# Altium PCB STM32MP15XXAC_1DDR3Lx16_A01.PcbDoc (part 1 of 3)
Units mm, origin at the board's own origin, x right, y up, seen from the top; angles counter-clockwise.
Board outline 89 x 120 mm, 4 copper layers (Top Layer, Signal Layer 1, Signal Layer 2, Bottom Layer), stack 1.571 mm thick; 133 components, 92 nets, 915 pads, 400 vias.
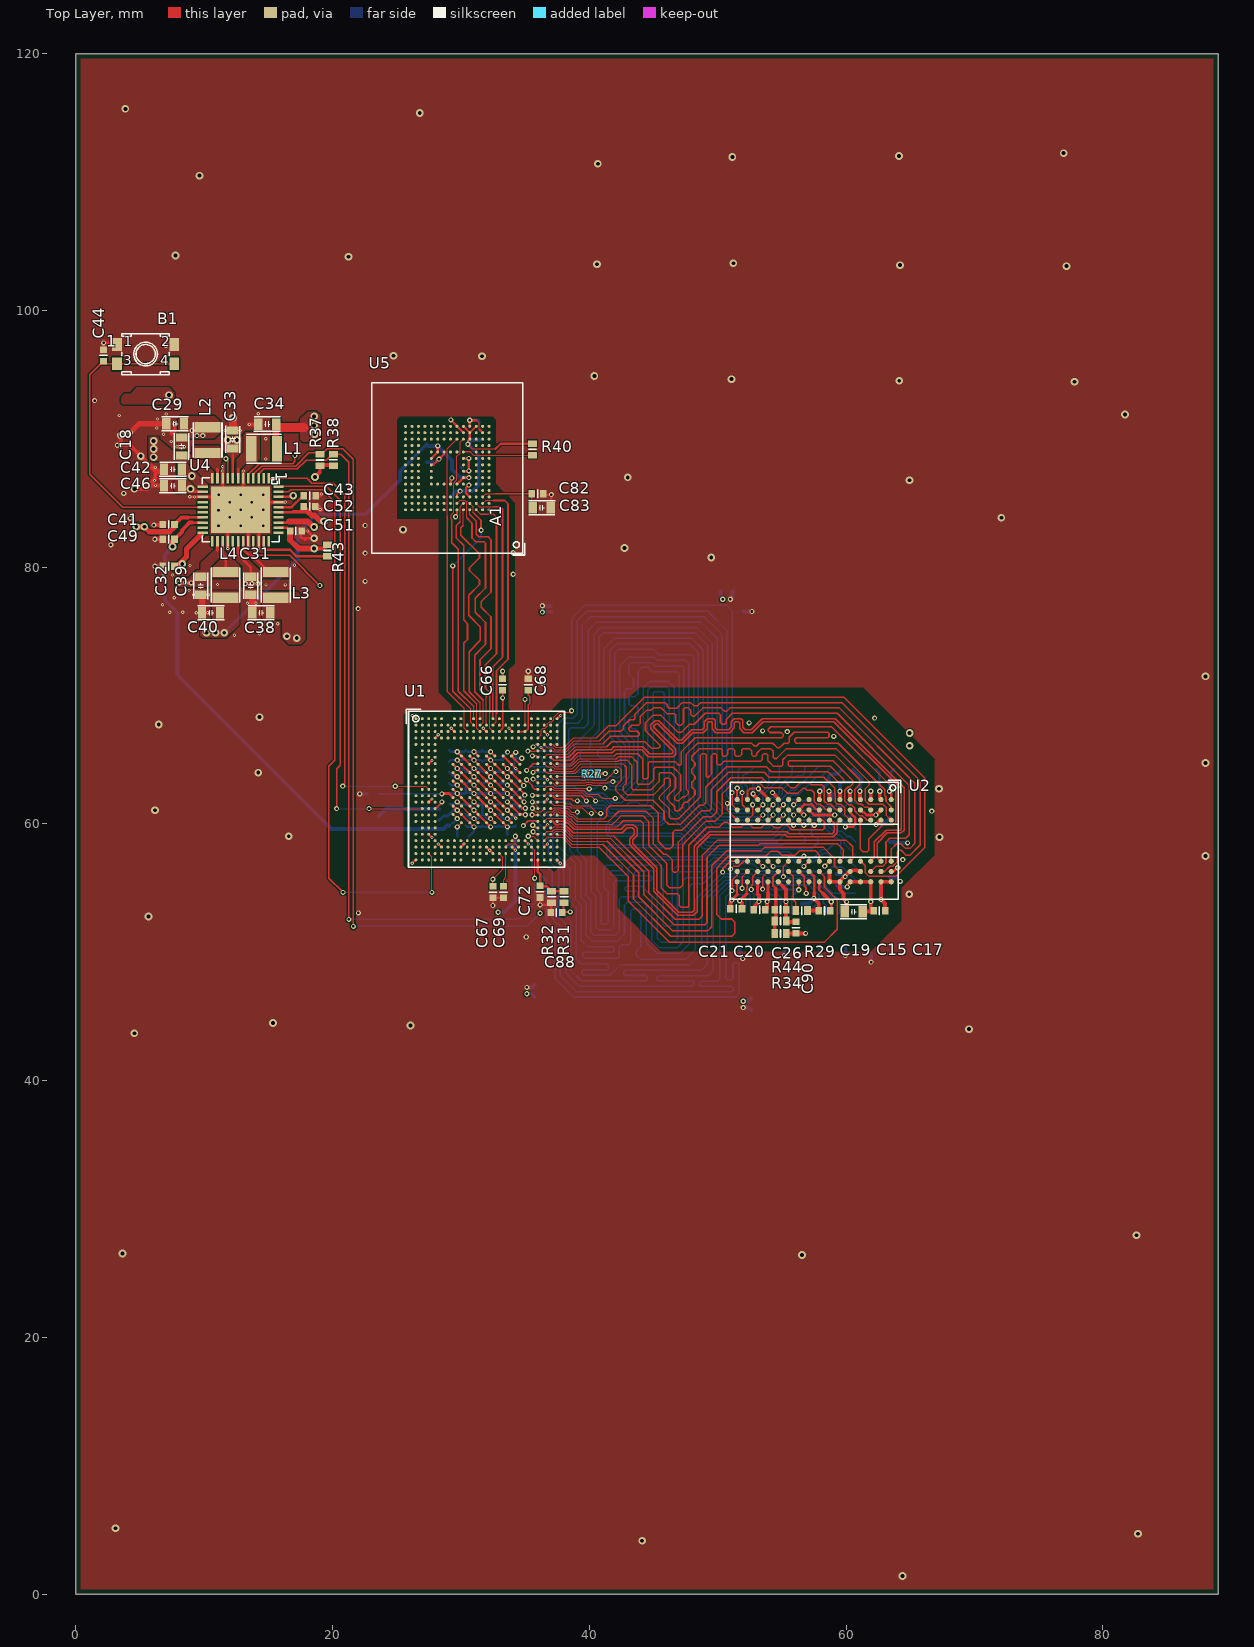
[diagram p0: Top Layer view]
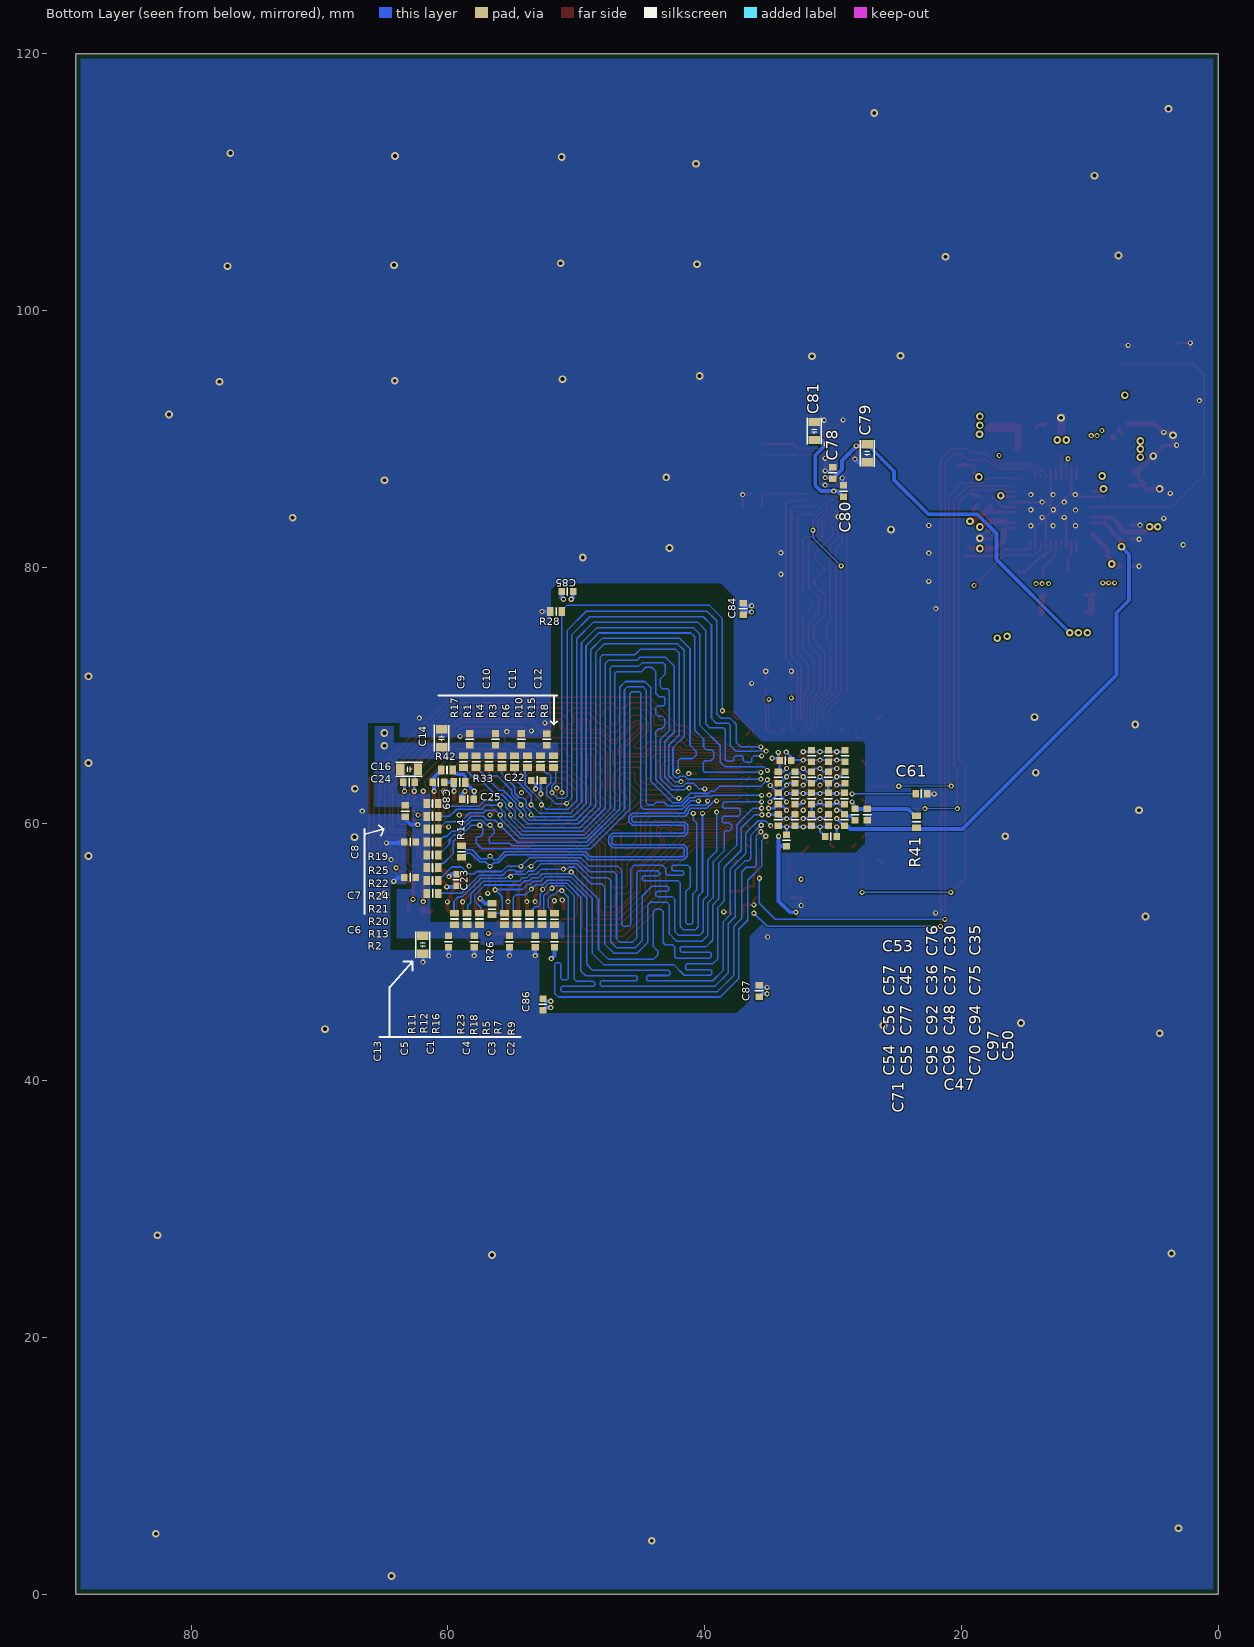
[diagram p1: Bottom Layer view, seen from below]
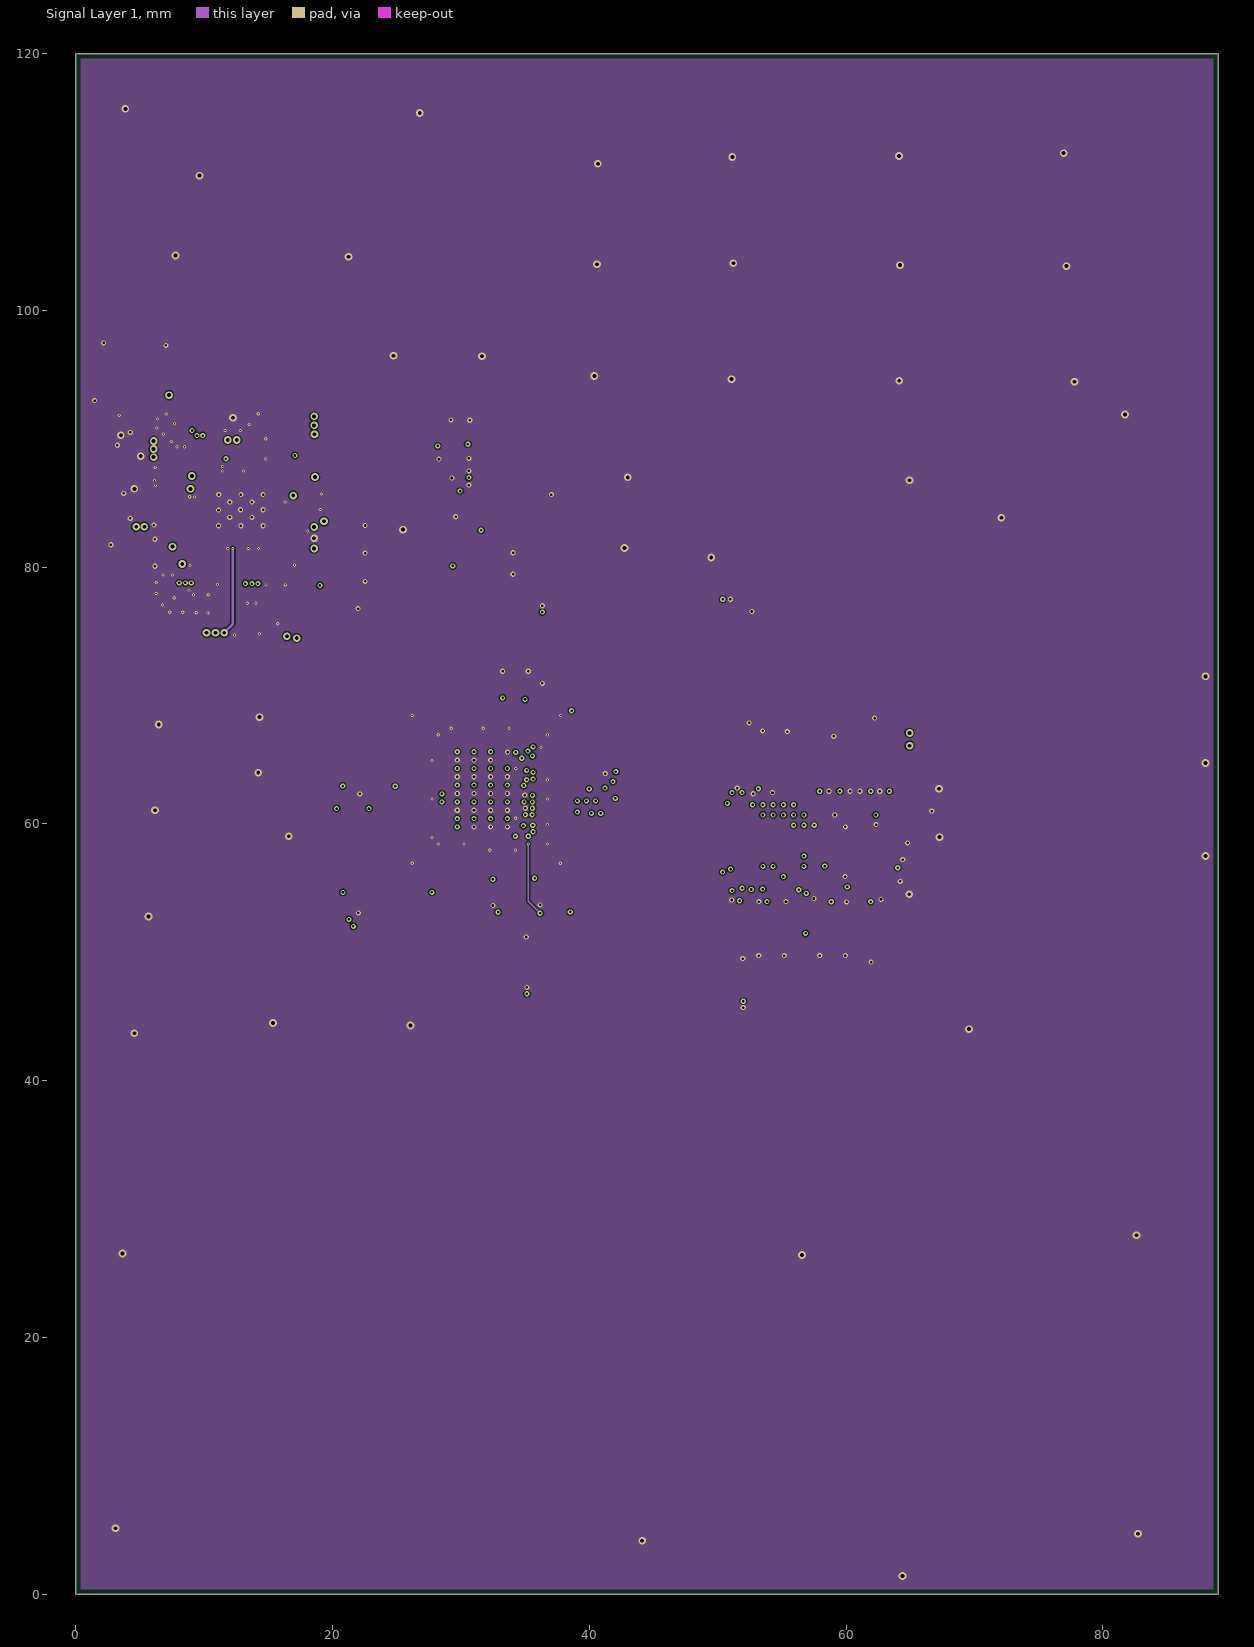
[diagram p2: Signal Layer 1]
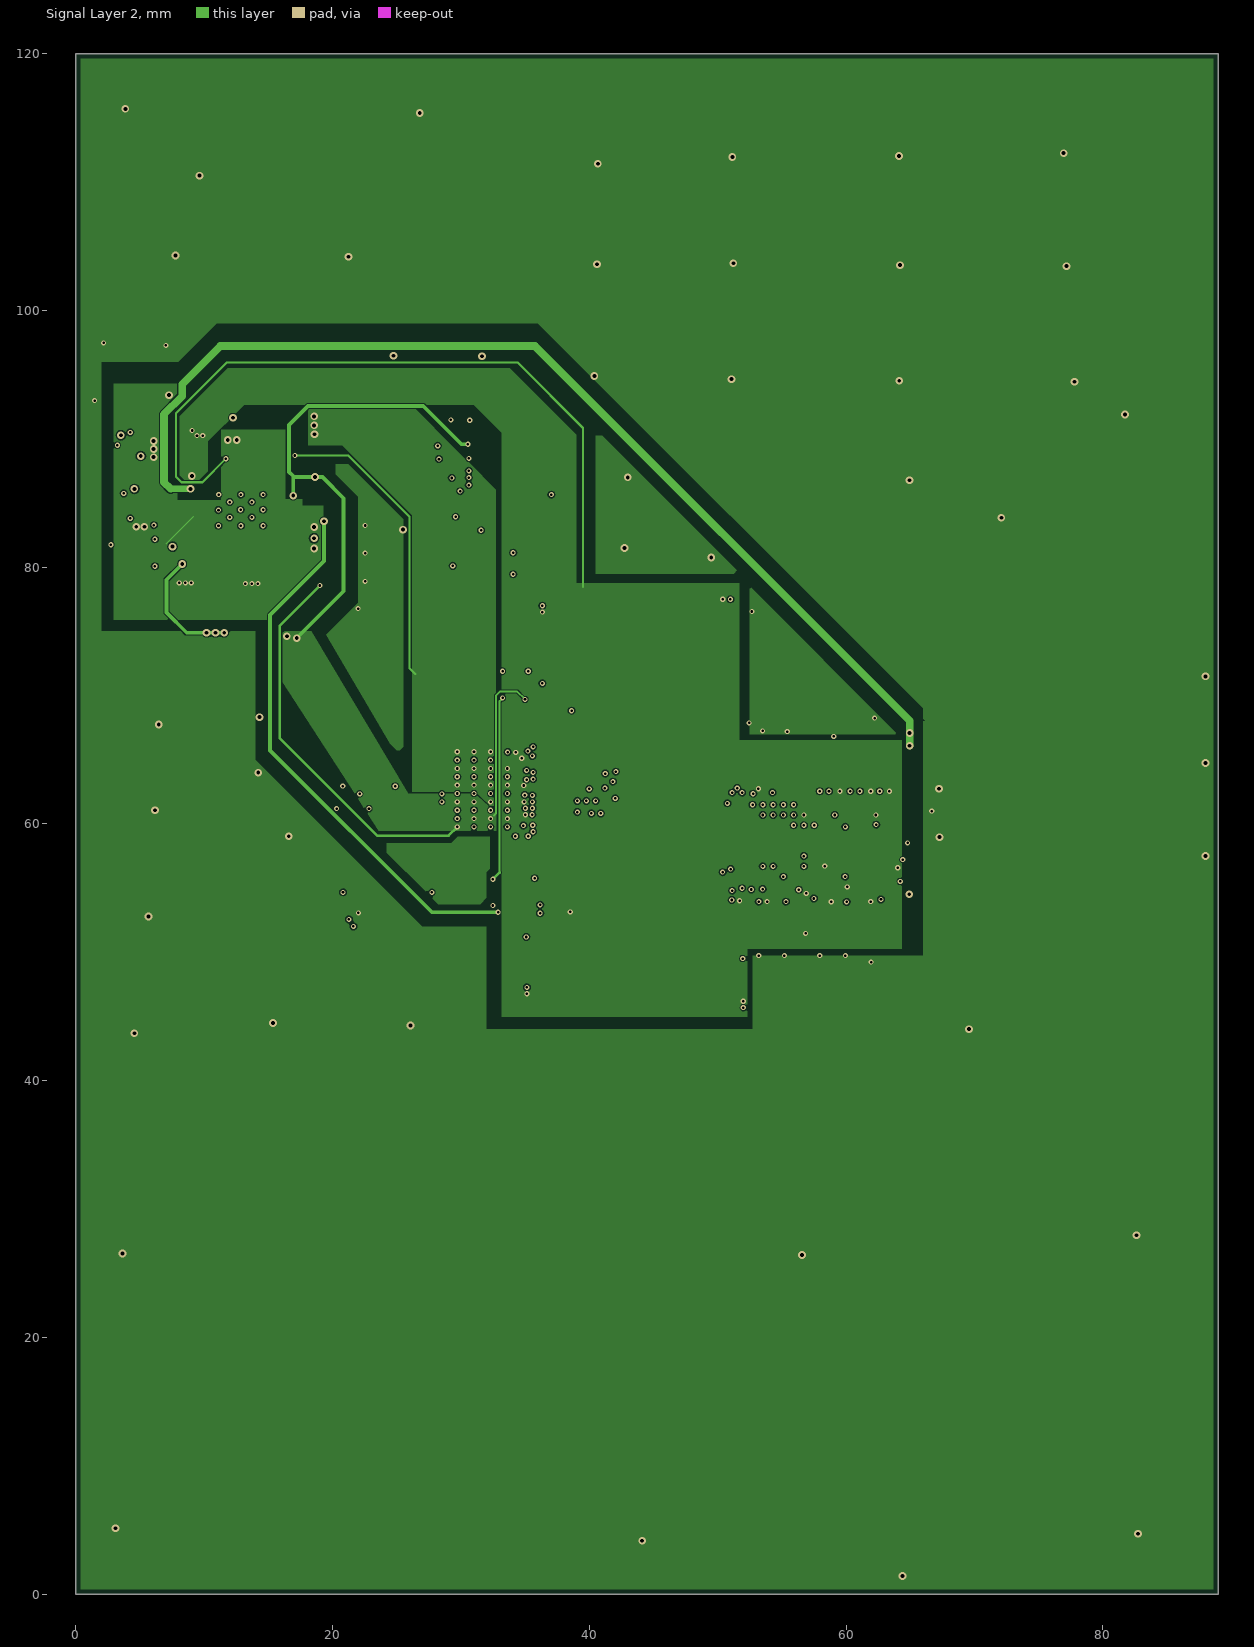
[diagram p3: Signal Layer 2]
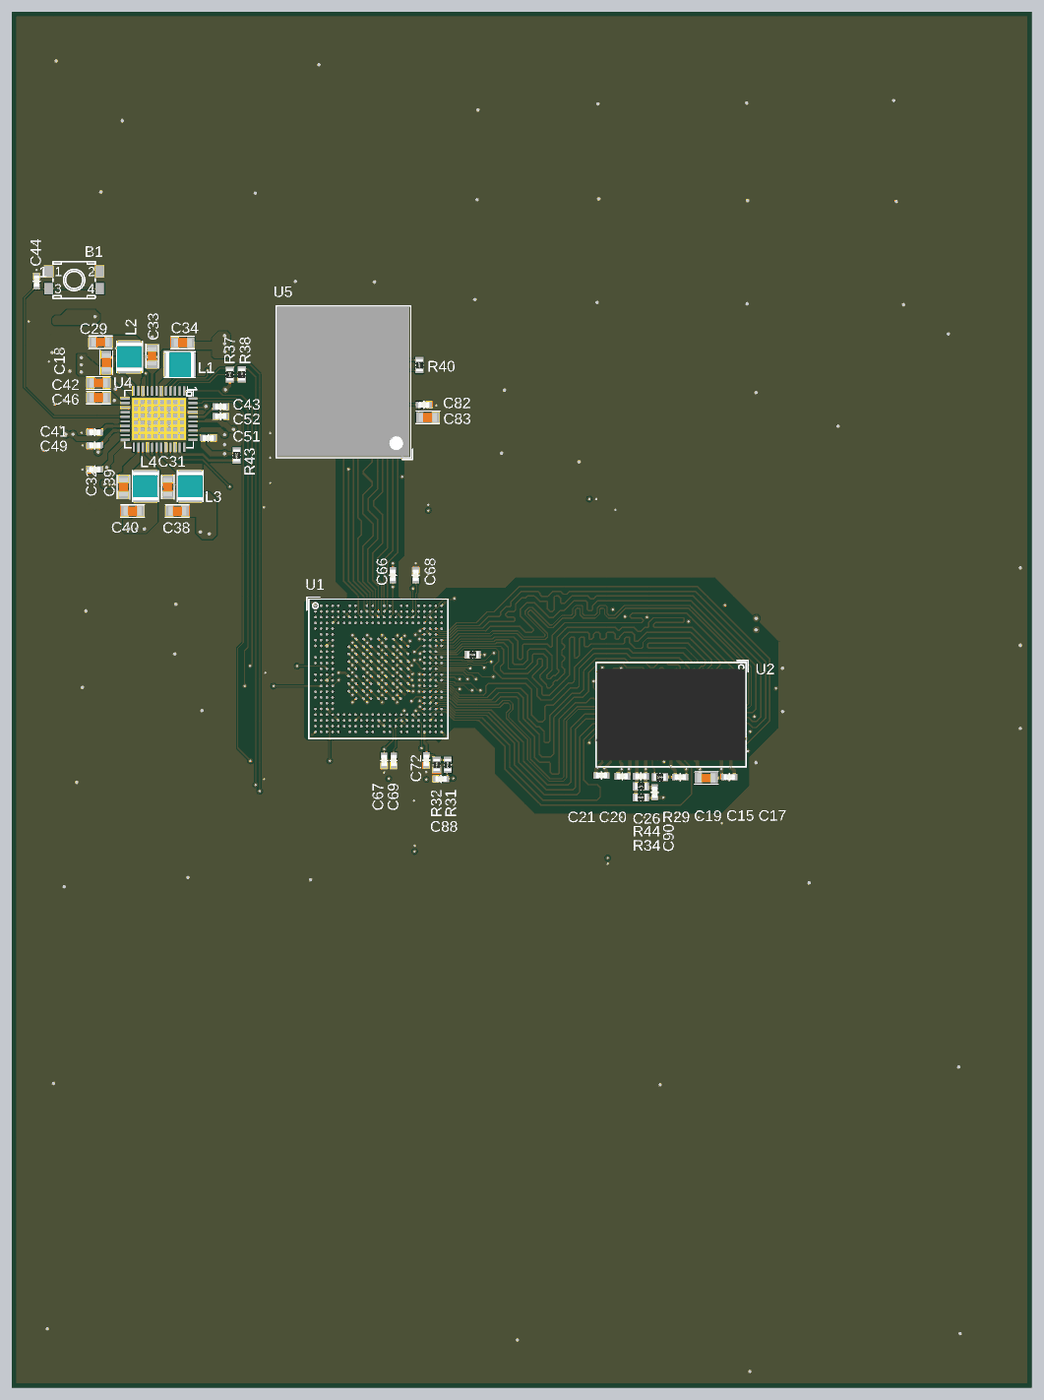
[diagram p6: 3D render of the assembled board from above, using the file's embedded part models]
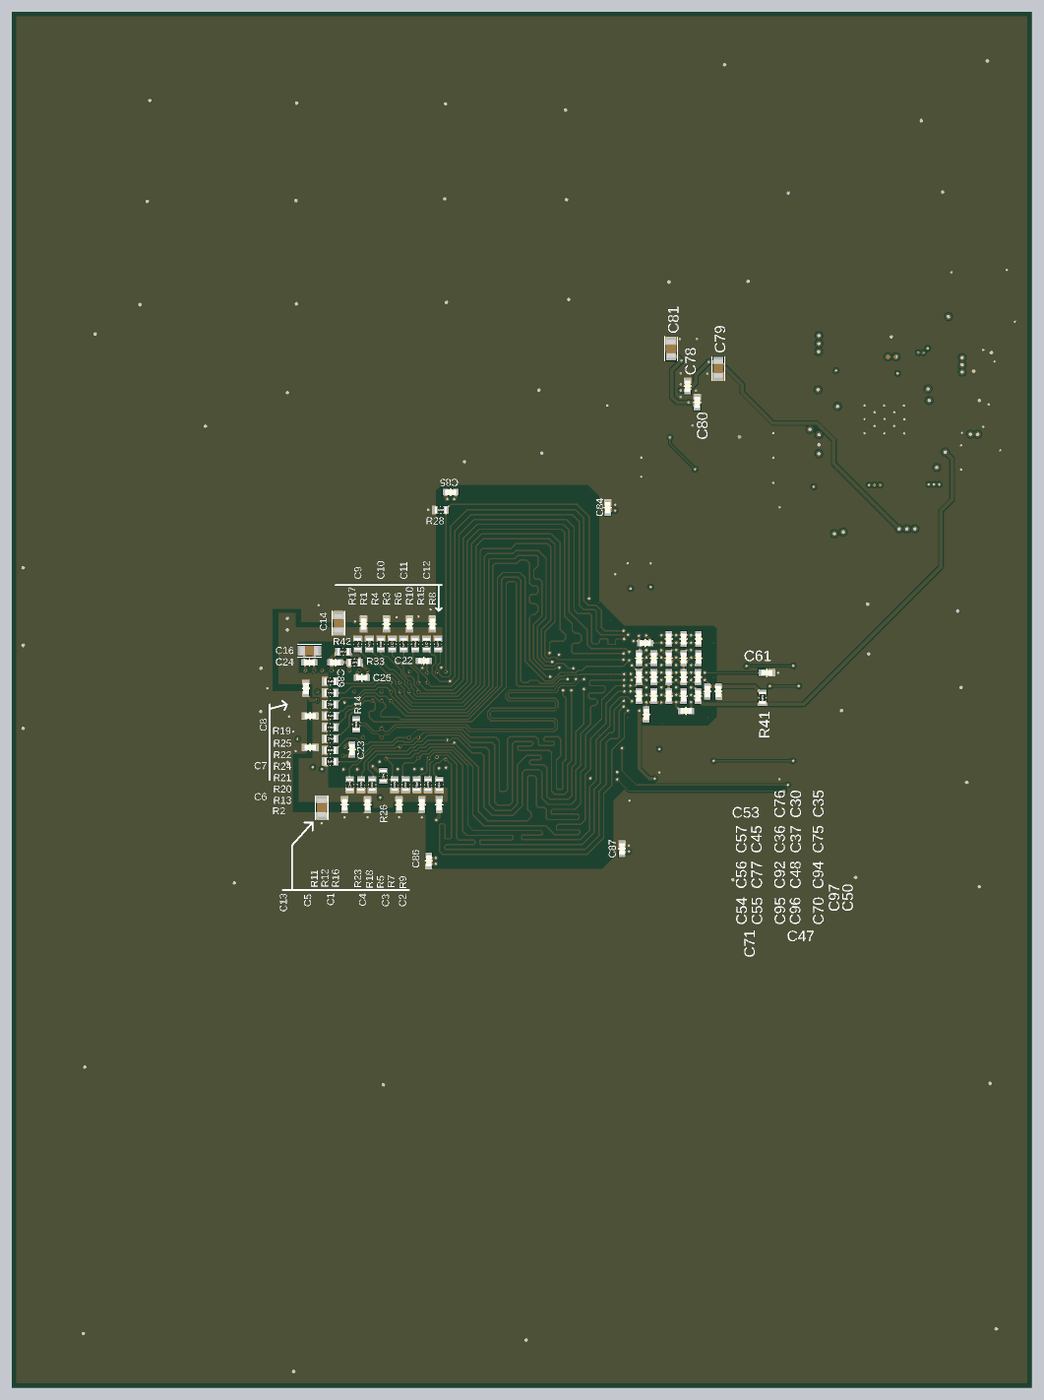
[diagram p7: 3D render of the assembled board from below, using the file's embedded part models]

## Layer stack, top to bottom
Top Solder: solder mask 0.0203, Solder Resist, Dk 3.5
Top Layer: signal copper 0.037
Dielectric 1: core 0.0986, FR-4, Dk 4.1
Signal Layer 1: signal copper 0.035
Dielectric 2: prepreg 1.23, Dk 4.25
Signal Layer 2: signal copper 0.035
Dielectric 3: core 0.0986, Dk 4.1
Bottom Layer: signal copper 0.037
Bottom Solder: solder mask 0.0203, Solder Resist, Dk 3.5

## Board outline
89,120 89,0 0,0 0,120

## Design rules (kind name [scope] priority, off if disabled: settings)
BoardOutlineClearance [All] p1: gap=0.4 ignorepadtopadclearanceinfootprint=FALSE
Clearance diff [InNetClass('diff')] p1: gap=0.1 ignorepadtopadclearanceinfootprint=FALSE except(0: Arc-Hole Track-Hole SMDPad-Hole THPad-Hole Via-Hole Fill-Hole Poly-Hole Region-Hole Text-Hole; 0.08: Track-SMDPad; 0.13: Track-Track; 0.15: Arc-Fill Track-Fill SMDPad-Fill THPad-Fill Via-Fill Fill-Fill; 0.2: Arc-THPad SMDPad-SMDPad SMDPad-THPad THPad-THPad)
Clearance [InNetClass('All Nets')] p2: gap=0.1 ignorepadtopadclearanceinfootprint=FALSE except(0: Arc-Hole Track-Hole SMDPad-Hole THPad-Hole Via-Hole Fill-Hole Poly-Hole Region-Hole Text-Hole; 0.08: Track-Track Track-SMDPad; 0.15: Arc-Fill Track-Fill SMDPad-Fill THPad-Fill Via-Fill Fill-Fill)
ComponentClearance [All] p1 off: gap=0.025 collisioncheckmode=3 verticalgap=2540 showdistances=TRUE
DiffPairsRouting [All] p1: maxlimit=0.13 minlimit=0.13 mostfreqgap=0.13 toplayer_minwidth=0.09 toplayer_maxwidth=0.13 toplayer_prefwidth=0.1 midlayer1_minwidth=0.09 midlayer1_maxwidth=0.13 midlayer1_prefwidth=0.1 midlayer2_minwidth=0.09 midlayer2_maxwidth=0.13 midlayer2_prefwidth=0.1 bottomlayer_minwidth=0.09 bottomlayer_maxwidth=0.13 bottomlayer_prefwidth=0.1 maxuncoupledlength=0.5
FanoutControl Fanout_BGA [IsBGA] p1: bgadir=Out bgaviamode=Closest fanoutstyle=Auto fanoutdirection=Alternating viagrid=0.025 // Fanout_BGA (Default Rule)
FanoutControl Fanout_LCC [IsLCC] p2: bgadir=Out bgaviamode=Closest fanoutstyle=Auto fanoutdirection=Alternating viagrid=0.025 // Fanout_LCC (Default Rule)
FanoutControl Fanout_SOIC [IsSOIC] p3: bgadir=Out bgaviamode=Closest fanoutstyle=Auto fanoutdirection=Alternating viagrid=0.025 // Fanout_SOIC (Default Rule)
FanoutControl Fanout_Small [(CompPinCount < 5)] p4: bgadir=Out bgaviamode=Closest fanoutstyle=Auto fanoutdirection=OutThenIn viagrid=0.025 // Fanout_Small (Default Rule)
FanoutControl Fanout_Default [All] p5: bgadir=Out bgaviamode=Closest fanoutstyle=Auto fanoutdirection=Alternating viagrid=0.025 // Fanout_Default (Default Rule)
Height [All] p1 off: minheight=0 maxheight=100 prefheight=0.5
HoleSize [All] p1: absolutevalues=TRUE maxlimit=10 minlimit=0.15 maxpercent=80.000 minpercent=20.000
HoleToHoleClearance [All] p1: gap=0.25 allowstackedmicrovias=TRUE
Length Length_SDMMC1 [InNetClass('NETC_SDMMC1')] p1: maxlimit=86 minlimit=81
MatchedLengths [All] p1: tolerance=25.4 checknetsindiffpair=FALSE checkdiffpairvsdiffpair=TRUE checkxsignals=TRUE checkothers=TRUE
MinimumSolderMaskSliver [All] p1: minsoldermaskwidth=0
PlaneClearance [All] p1: clearance=0.6
PlaneConnect [All] p1: planeconnectstyle=Direct reliefexpansion=0.508 reliefentries=4 reliefconductorwidth=0.254 reliefairgap=0.254
PolygonConnect PolygonConnect_notr [All vs (IsNamedPolygon('NO TR'))] p1: connectstyle=Direct reliefconductorwidth=0.254 reliefentries=4 polygonreliefangle="90 Angle" airgapwidth=0.254
PolygonConnect PolygonConnect_VTT_DDR [All vs IsNamedPolygon('VTT_DDR_BOT')] p2: connectstyle=Direct reliefconductorwidth=0.254 reliefentries=4 polygonreliefangle="45 Angle" airgapwidth=0.254
PolygonConnect [All] p3: connectstyle=Direct reliefconductorwidth=0.254 reliefentries=4 polygonreliefangle="45 Angle" airgapwidth=0.254
RoomDefinition U_1DDR3L_16bits [InComponentClass('U_1DDR3L_16bits')] p1: confinementstyle=ConfineIn formatcopy=TRUE lockcomponents=FALSE outline 90.023,1.598 95.023,1.598 95.023,8.598 90.023,8.598
RoomDefinition U_STM32_MPU_IOs [InComponentClass('U_STM32_MPU_IOs')] p2 off: confinementstyle=ConfineIn formatcopy=TRUE lockcomponents=FALSE outline 88.575,2.075 139.375,2.075 139.375,27.475 88.575,27.475
RoomDefinition U_Power_MPU [InComponentClass('U_Power_MPU')] p3 off: confinementstyle=ConfineIn formatcopy=TRUE lockcomponents=FALSE outline 87.122,16.916 100.898,16.916 100.898,22.892 87.122,22.892
RoomDefinition U_eMMC [InComponentClass('U_eMMC')] p4 off: confinementstyle=ConfineIn formatcopy=TRUE lockcomponents=FALSE outline 87.122,1.416 129.449,1.416 129.449,15.666 87.122,15.666
RoomDefinition U_Power_PMIC [InComponentClass('U_Power_PMIC')] p5 off: confinementstyle=ConfineIn formatcopy=TRUE lockcomponents=FALSE outline 87.122,8.666 203.578,8.666 203.578,17.666 87.122,17.666
RoutingVias RoutingVias_GND [InNetClass('GND')] p1: holewidth=0.3 width=0.6 viastyle="Through Hole" minholewidth=0.2 minwidth=0.4 maxholewidth=0.3 maxwidth=0.6
RoutingVias RoutingVias_ALIMS [InNetClass('ALIMS')] p2: holewidth=0.3 width=0.6 viastyle="Through Hole" minholewidth=0.2 minwidth=0.4 maxholewidth=0.3 maxwidth=0.6
RoutingVias [All] p3: holewidth=0.2 width=0.4 viastyle="Through Hole" minholewidth=0.2 minwidth=0.4 maxholewidth=0.3 maxwidth=0.6
SilkToSilkClearance [All] p1: silktosilkclearance=0
SilkToSolderMaskClearance [IsPad] p1: minsilkscreentomaskgap=0 clearancetoexposedcopper=TRUE
SolderMaskExpansion [All] p1: expansion=0.05
Width VDD_DDR [InNet('VDD_DDR')] p1: maxlimit=1.5 minlimit=0.1 preferedwidth=0.3 minimp=50.000000 maximp=50.000000 favimp=50.000000
Width Width_VCORE [InNet('VDD_CORE')] p2: maxlimit=0.2 minlimit=0.175 preferedwidth=0.2
Width Width_gnd [InNet('GND')] p3: maxlimit=0.3 minlimit=0.1 preferedwidth=0.3
Width [All] p4: maxlimit=1 minlimit=0.09 preferedwidth=0.12 minimp=50.000000 maximp=50.000000 favimp=50.000000
15 further rules are at their usual default settings.

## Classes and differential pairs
net class eMMC_SDIO2_D[0..7]: eMMC_SDIO2_D0 eMMC_SDIO2_D1 eMMC_SDIO2_D2 eMMC_SDIO2_D3 eMMC_SDIO2_D4 eMMC_SDIO2_D5 eMMC_SDIO2_D6 eMMC_SDIO2_D7
component class U_STM32_MPU_IOs: C72 C88 R27 R31 R32 R37 R38 U1
component class U_eMMC: C78 C79 C80 C81 C82 C83 R40 U5
component class U_Power_PMIC: B1 C18 C29 C31 C32 C33 C34 C38 C39 C40 C41 C42 C43 C44 C46 C49 C51 C52 L1 L2 L3 L4 R43 U4
component class U_Power_MPU: C30 C35 C36 C37 C45 C47 C48 C50 C53 C54 C55 C56 C57 C61 C66 C67 C68 C69 C70 C71 C75 C76 C77 C92 C94 C95 C96 C97 R41
component class U_1DDR3L_16bits: C1 C2 C3 C4 C5 C6 C7 C8 C9 C10 C11 C12 C13 C14 C15 C16 C17 C19 C20 C21 C22 C23 C24 C25 C26 C84 C85 C86 C87 C89 C90 R1 R2 R3 R4 R5 R6 R7 R8 R9 R10 R11 R12 R13 R14 R15 R16 R17 R18 R19 R20 R21 R22 R23 R24 R25 R26 R28 R29 R33 R34 R42 R44 U2
polygon class POLY_DIRECT_ALL: NETC906_2_L01_P192
differential pair class DIFF_DQS0: DDR_DQS0
differential pair class DIFF_DQS1: DDR_DQS1
differential pair class DIFF_CLK: DDR_CLK
differential pair DDR_DQS1: +DDR_DQS1_P -DDR_DQS1_N
differential pair DDR_DQS0: +DDR_DQS0_P -DDR_DQS0_N
differential pair DDR_CLK: +DDR_CLK_P -DDR_CLK_N

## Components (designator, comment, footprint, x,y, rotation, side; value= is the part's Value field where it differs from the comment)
B1 "" SWI_JIUBABA_C-TS-02H-2-5-B-V-T_R_BLUE 5.45,96.6 r0 top value=SW-PUSH-TS-02H-Blue
C1 "" C0402 57.955,50.845 r270 bottom value=100nF
C2 "" C0402 51.705,50.845 r270 bottom value=100nF
C3 "" C0402 53.205,50.845 r270 bottom value=100nF
C4 "" C0402 55.205,50.845 r270 bottom value=100nF
C5 "" C0402 59.955,50.845 r270 bottom value=100nF
C6 "" C0402 62.955,55.845 r0 bottom value=100nF
C7 "" C0402 62.955,58.595 r0 bottom value=100nF
C8 "" C0402 63.325,61 r270 bottom value=100nF
C9 "" C0402 58.3,66.6 r90 bottom value=100nF
C10 "" C0402 56.3,66.6 r90 bottom value=100nF
C11 "" C0402 54.3,66.6 r90 bottom value=100nF
C12 "" C0402 52.3,66.595 r90 bottom value=100nF
C13 "" C0603 61.955,50.595 r90 bottom value=22uF
C14 "" C0603 60.5,66.675 r270 bottom value=22uF
C15 "" C0603 60.6,53.175 r0 top value=10uF
C16 "" C0603 63.025,64.275 r0 bottom value=10uF
C17 "" C0402 62.6,53.25 r0 top value=100nF
C18 "" C0603 8.25,89.4 r270 top value=10uF
C19 "" C0402 58.325,53.25 r180 top value=100nF
C20 "" C0402 53.275,53.325 r180 top value=100nF
C21 "" C0402 51.45,53.4 r180 top value=100nF
C22 "" C0402 53.05,63.4 r180 bottom value=100nF
C23 "" C0402 59.3,55.65 r90 bottom value=100nF
C24 "" C0402 63.025,63.25 r180 bottom value=100nF
C25 "" C0402 58.45,61.925 r0 bottom value=100nF
C26 "" C0402 54.9,53.325 r0 top value=100nF
C29 "" C0603 7.75,91.175 r0 top value=22uF
C30 "" C0402 30.375,65.3 r90 bottom value=1uF
C31 "" C0603 13.625,78.55 r90 top value=10uF
C32 "" C0402 7.25,80.075 r0 top value=1uF
C33 "" C0603 12.25,89.95 r270 top value=10uF
C34 "" C0603 14.925,91.15 r0 top value=22uF
C35 "" C0402 29.075,65.3 r90 bottom value=1uF
C36 "" C0402 31.675,63.625 r90 bottom value=1uF
C37 "" C0402 30.375,63.625 r90 bottom value=1uF
C38 "" C0603 14.45,76.45 r0 top value=22uF
C39 "" C0603 9.75,78.55 r90 top value=10uF
C40 "" C0603 10.55,76.45 r0 top value=22uF
C41 "" C0402 7.25,83.325 r0 top value=1uF
C42 "" C0603 7.575,87.625 r0 top value=10uF
C43 "" C0402 18.234,85.562 r0 top value=4.7uF
C44 "" C0402 2.175,96.5 r270 top value=10nF
C45 "" C0402 32.975,63.625 r270 bottom value=1uF
C46 "" C0603 7.575,86.35 r0 top value=10uF
C47 "" C0402 30.175,59.025 r180 bottom value=1uF
C48 "" C0402 30.375,61.975 r270 bottom value=1uF
C49 "" C0402 7.25,82.175 r0 top value=4.7uF
C50 "" C0402 27.35,60.725 r90 bottom value=1uF
C51 "" C0402 17.15,82.825 r180 top value=4.7uF
C52 "" C0402 18.225,84.725 r180 top value=4.7uF
C53 "" C0402 33.725,64.95 r0 bottom value=1uF
C54 "" C0402 34.275,60.325 r90 bottom value=1uF
C55 "" C0402 32.975,60.325 r90 bottom value=1uF
C56 "" C0402 34.275,61.975 r90 bottom value=1nF
C57 "" C0402 34.275,63.625 r90 bottom value=1nF
C61 "" C0402 23.125,62.35 r0 bottom value=100nF
C66 "Capacitor" C0402 33.25,70.85 r270 top value=100nF
C67 "Capacitor" C0402 32.5,54.7 r90 top value=2.2uF
C68 "Capacitor" C0402 35.25,70.85 r270 top value=2.2uF
C69 "Capacitor" C0402 33.325,54.7 r90 top value=2.2uF
C70 "" C0402 29.125,60.325 r270 bottom value=1uF
C71 "" C0402 33.625,58.725 r270 bottom value=100nF
C72 "" C0402 36.175,54.725 r90 top value=100nF
C75 "" C0402 29.075,63.625 r270 bottom value=1uF
C76 "" C0402 31.675,65.3 r90 bottom value=1uF
C77 "" C0402 32.975,61.975 r270 bottom value=1uF
C78 "" C0402 30.025,87.35 r270 bottom value=100nF
C79 "" C0603 27.35,88.875 r90 bottom value=2.2uF
C80 "" C0402 29.2,85.925 r270 bottom value=100nF
C81 "" C0603 31.475,90.6 r270 bottom value=2.2uF
C82 "" C0402 35.975,85.725 r180 top value=100nF
C83 "" C0603 36.3,84.625 r180 top value=2.2uF
C84 "" C0402 37,76.75 r90 bottom value=100nF
C85 "" C0402 50.7,78.1 r0 bottom value=100nF
C86 "" C0402 52.6,45.95 r270 bottom value=100nF
C87 "" C0402 35.75,47 r90 bottom value=100nF
C88 "" C0402 37.45,53.1 r0 top value=100nF
C89 "" C0402 60.75,63.25 r0 bottom value=100nF
C90 "" C0402 56.1,51.925 r90 top value=100nF
C92 "" C0402 31.675,61.975 r270 bottom value=1uF
C94 "" C0402 29.125,61.975 r270 bottom value=1uF
C95 "" C0402 31.675,60.325 r90 bottom value=1uF
C96 "" C0402 30.375,60.325 r90 bottom value=1uF
C97 "Capacitor" C0402 28.3,60.725 r90 bottom value=10nF
L1 "" IND_2520_TOKO_DFE252012P 14.675,89.225 r0 top value=1uH
L2 "" IND_2520_TOKO_DFE252012P 10.275,89.9 r90 top value=1uH
L3 "" IND_2520_TOKO_DFE252012P 15.575,78.625 r270 top value=1uH
L4 "" IND_2520_TOKO_DFE252012P 11.675,78.625 r270 top value=1uH
R1 "" R0402 57.8,64.85 r90 bottom value=56R
R2 "" R0402 61.2,54.6 r0 bottom value=56R
R3 "" R0402 55.8,64.85 r90 bottom value=56R
R4 "" R0402 56.8,64.85 r90 bottom value=56R
R5 "" R0402 53.65,52.6 r270 bottom value=56R
R6 "" R0402 54.8,64.85 r90 bottom value=56R
R7 "" R0402 52.675,52.6 r270 bottom value=56R
R8 "" R0402 51.8,64.85 r90 bottom value=56R
R9 "" R0402 51.705,52.595 r270 bottom value=56R
R10 "" R0402 53.8,64.85 r90 bottom value=56R
R11 "" R0402 59.5,52.6 r270 bottom value=56R
R12 "" R0402 58.525,52.6 r270 bottom value=56R
R13 "" R0402 61.205,55.595 r0 bottom value=56R
R14 "" R0402 58.955,57.845 r90 bottom value=100R
R15 "" R0402 52.8,64.85 r90 bottom value=56R
R16 "" R0402 57.55,52.6 r270 bottom value=56R
R17 "" R0402 58.8,64.85 r90 bottom value=56R
R18 "" R0402 54.625,52.6 r270 bottom value=56R
R19 "" R0402 61.205,61.595 r0 bottom value=56R
R20 "" R0402 61.205,56.595 r0 bottom value=56R
R21 "" R0402 61.205,57.595 r0 bottom value=56R
R22 "" R0402 61.205,59.595 r0 bottom value=56R
R23 "" R0402 55.6,52.6 r270 bottom value=56R
R24 "" R0402 61.205,58.595 r0 bottom value=56R
R25 "" R0402 61.205,60.595 r0 bottom value=56R
R26 "" R0402 56.58,53.37 r270 bottom value=10K
R27 "" R0402 40.225,63.925 r0 top value="240R 1%"
R28 "" R0402 51.575,76.55 r180 bottom value=10K
R29 "" R0402 56.55,53.25 r180 top value="240R 1%"
R31 "" R0402 38.05,54.325 r270 top value=1K
R32 "" R0402 37.075,54.325 r90 top value=1K
R33 "" R0402 59.1,63.25 r0 bottom value=1K
R34 "" R0402 54.9,51.475 r0 top value=1K
R37 "" R0402 19.025,88.35 r90 top value=1K5
R38 "" R0402 20.074,88.363 r90 top value=1K5
R40 "" R0402 35.575,89.175 r90 top value=10K
R41 "" R0402 23.5,60.175 r90 bottom value=0R
R42 "" R0402 60.075,64.2 r180 bottom value=1K
R43 "" R0402 19.625,81.3 r90 top value=47K
R44 "" R0402 54.9,52.45 r180 top value=1K
U1 "" ICC_TFBGA361_12X12_STM32MP157CAC3_P050-065 32,62.7 r0 top locked value=STM32MP157CAC3
U2 "NT5CC256M16ER-EK" ICC_VFBGA96_9X13_P080 57.525,58.7 r270 top
U4 "" ICC_WFQFN44-EPAD_5X6_P040 12.85,84.475 r270 top value=STPMU1A
U5 "" ICC_P-WFBGA153_13X11P5_P050 28.95,87.725 r90 top locked value=THGBMDG5D1LBAIL

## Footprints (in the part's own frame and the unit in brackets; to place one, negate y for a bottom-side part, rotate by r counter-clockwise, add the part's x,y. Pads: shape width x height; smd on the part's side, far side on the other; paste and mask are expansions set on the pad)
C0402 [mm]
  rect 0.51x0.56 smd mask+0.05: 1(-0.45,0) 2(0.45,0)
  silkscreen extent 0,-0.3 0,0.3, body extent -0.5,-0.3 0.5,0.3, height 0.4
C0603 [mm]
  rect 0.64x0.89 smd mask+0.05: 1(-0.7,0) 2(0.7,0)
  silkscreen extent -1.05,-0.55 1.02,0.55, body extent -0.9,-0.5 0.9,0.5, height 1.4
ICC_P-WFBGA153_13X11P5_P050 [mm]
  round 0.23 smd mask+0.05: A1(-3.25,-3.25) A2(-3.25,-2.75) A3(-3.25,-2.25) A4(-3.25,-1.75) A5(-3.25,-1.25) A6(-3.25,-0.75) A7(-3.25,-0.25) A8(-3.25,0.25) A9(-3.25,0.75) A10(-3.25,1.25) A11(-3.25,1.75) A12(-3.25,2.25) A13(-3.25,2.75) A14(-3.25,3.25) B1(-2.75,-3.25) B2(-2.75,-2.75) B3(-2.75,-2.25) B4(-2.75,-1.75) B5(-2.75,-1.25) B6(-2.75,-0.75) B7(-2.75,-0.25) B8(-2.75,0.25) B9(-2.75,0.75) B10(-2.75,1.25) B11(-2.75,1.75) B12(-2.75,2.25) B13(-2.75,2.75) B14(-2.75,3.25) C1(-2.25,-3.25) C2(-2.25,-2.75) C3(-2.25,-2.25) C4(-2.25,-1.75) C5(-2.25,-1.25) C6(-2.25,-0.75) C7(-2.25,-0.25) C8(-2.25,0.25) C9(-2.25,0.75) C10(-2.25,1.25) C11(-2.25,1.75) C12(-2.25,2.25) C13(-2.25,2.75) C14(-2.25,3.25) D1(-1.75,-3.25) D2(-1.75,-2.75) D3(-1.75,-2.25) D4(-1.75,-1.75) D12(-1.75,2.25) D13(-1.75,2.75) D14(-1.75,3.25) E1(-1.25,-3.25) E2(-1.25,-2.75) E3(-1.25,-2.25) E5(-1.25,-1.25) E6(-1.25,-0.75) E7(-1.25,-0.25) E8(-1.25,0.25) E9(-1.25,0.75) E10(-1.25,1.25) E12(-1.25,2.25) E13(-1.25,2.75) E14(-1.25,3.25) F1(-0.75,-3.25) F2(-0.75,-2.75) F3(-0.75,-2.25) F5(-0.75,-1.25) F10(-0.75,1.25) F12(-0.75,2.25) F13(-0.75,2.75) F14(-0.75,3.25) G1(-0.25,-3.25) G2(-0.25,-2.75) G3(-0.25,-2.25) G5(-0.25,-1.25) G10(-0.25,1.25) G12(-0.25,2.25) G13(-0.25,2.75) G14(-0.25,3.25) H1(0.25,-3.25) H2(0.25,-2.75) H3(0.25,-2.25) H5(0.25,-1.25) H10(0.25,1.25) H12(0.25,2.25) H13(0.25,2.75) H14(0.25,3.25) J1(0.75,-3.25) J2(0.75,-2.75) J3(0.75,-2.25) J5(0.75,-1.25) J10(0.75,1.25) J12(0.75,2.25) J13(0.75,2.75) J14(0.75,3.25) K1(1.25,-3.25) K2(1.25,-2.75) K3(1.25,-2.25) K5(1.25,-1.25) K6(1.25,-0.75) K7(1.25,-0.25) K8(1.25,0.25) K9(1.25,0.75) K10(1.25,1.25) K12(1.25,2.25) K13(1.25,2.75) K14(1.25,3.25) L1(1.75,-3.25) L2(1.75,-2.75) L3(1.75,-2.25) L12(1.75,2.25) L13(1.75,2.75) L14(1.75,3.25) M1(2.25,-3.25) M2(2.25,-2.75) M3(2.25,-2.25) M4(2.25,-1.75) M5(2.25,-1.25) M6(2.25,-0.75) M7(2.25,-0.25) M8(2.25,0.25) M9(2.25,0.75) M10(2.25,1.25) M11(2.25,1.75) M12(2.25,2.25) M13(2.25,2.75) M14(2.25,3.25) N1(2.75,-3.25) N2(2.75,-2.75) N3(2.75,-2.25) N4(2.75,-1.75) N5(2.75,-1.25) N6(2.75,-0.75) N7(2.75,-0.25) N8(2.75,0.25) N9(2.75,0.75) N10(2.75,1.25) N11(2.75,1.75) N12(2.75,2.25) N13(2.75,2.75) N14(2.75,3.25) P1(3.25,-3.25) P2(3.25,-2.75) P3(3.25,-2.25) P4(3.25,-1.75) P5(3.25,-1.25) P6(3.25,-0.75) P7(3.25,-0.25) P8(3.25,0.25) P9(3.25,0.75) P10(3.25,1.25) P11(3.25,1.75) P12(3.25,2.25) P13(3.25,2.75) P14(3.25,3.25)
  silkscreen extent -6.78,-6.02 6.63,5.87, body extent -6.55,-5.8 6.55,5.8, height 1
ICC_TFBGA361_12X12_STM32MP157CAC3_P050-065 [mm] "IPC"
  round 0.23 smd mask+0.05: 1A2(-1.95,2.6) 1A3(-1.3,2.6) 1A4(-0.65,2.6) 1A5(0,2.6) 1A6(0.65,2.6) 1A7(1.3,2.6) 1A8(1.95,2.6) 1B1(-2.6,1.95) 1B2(-1.95,1.95) 1B3(-1.3,1.95) 1B4(-0.65,1.95) 1B5(0,1.95) 1B6(0.65,1.95) 1B7(1.3,1.95) 1B8(1.95,1.95) 1B9(2.6,1.95) 1C1(-2.6,1.3) 1C2(-1.95,1.3) 1C3(-1.3,1.3) 1C4(-0.65,1.3) 1C5(0,1.3) 1C6(0.65,1.3) 1C7(1.3,1.3) 1C8(1.95,1.3) 1C9(2.6,1.3) 1D1(-2.6,0.65) 1D2(-1.95,0.65) 1D3(-1.3,0.65) 1D4(-0.65,0.65) 1D5(0,0.65) 1D6(0.65,0.65) 1D7(1.3,0.65) 1D8(1.95,0.65) 1D9(2.6,0.65) 1E1(-2.6,0) 1E2(-1.95,0) 1E3(-1.3,0) 1E4(-0.65,0) 1E5(0,0) 1E6(0.65,0) 1E7(1.3,0) 1E8(1.95,0) 1E9(2.6,0) 1F1(-2.6,-0.65) 1F2(-1.95,-0.65) 1F3(-1.3,-0.65) 1F4(-0.65,-0.65) 1F5(0,-0.65) 1F6(0.65,-0.65) 1F7(1.3,-0.65) 1F8(1.95,-0.65) 1F9(2.6,-0.65) 1G1(-2.6,-1.3) 1G2(-1.95,-1.3) 1G3(-1.3,-1.3) 1G4(-0.65,-1.3) 1G5(0,-1.3) 1G6(0.65,-1.3) 1G7(1.3,-1.3) 1G8(1.95,-1.3) 1G9(2.6,-1.3) 1H1(-2.6,-1.95) 1H2(-1.95,-1.95) 1H3(-1.3,-1.95) 1H4(-0.65,-1.95) 1H5(0,-1.95) 1H6(0.65,-1.95) 1H7(1.3,-1.95) 1H8(1.95,-1.95) 1H9(2.6,-1.95) 1J2(-1.95,-2.6) 1J3(-1.3,-2.6) 1J4(-0.65,-2.6) 1J5(0,-2.6) 1J6(0.65,-2.6) 1J7(1.3,-2.6) 1J8(1.95,-2.6) A1(-5.5,5.5) A2(-5,5.5) A3(-4.5,5.5) A4(-4,5.5) A5(-3.5,5.5) A7(-2.5,5.5) A8(-2,5.5) A10(-1,5.5) A11(-0.5,5.5) A13(0.5,5.5) A14(1,5.5) A16(2,5.5) A17(2.5,5.5) A19(3.5,5.5) A20(4,5.5) A21(4.5,5.5) A22(5,5.5) A23(5.5,5.5) AA1(-5.5,-4.5) AA2(-5,-4.5) AA3(-4.5,-4.5) AA4(-4,-4.5) AA5(-3.5,-4.5) AA6(-3,-4.5) AA7(-2.5,-4.5) AA8(-2,-4.5) AA9(-1.5,-4.5) AA10(-1,-4.5) AA11(-0.5,-4.5) AA12(0,-4.5) AA13(0.5,-4.5) AA14(1,-4.5) AA15(1.5,-4.5) AA16(2,-4.5) AA17(2.5,-4.5) AA18(3,-4.5) AA19(3.5,-4.5) AA20(4,-4.5) AA21(4.5,-4.5) AA22(5,-4.5) AA23(5.5,-4.5) AB1(-5.5,-5) AB2(-5,-5) AB3(-4.5,-5) AB4(-4,-5) AB5(-3.5,-5) AB6(-3,-5) AB7(-2.5,-5) AB8(-2,-5) AB9(-1.5,-5) AB10(-1,-5) AB11(-0.5,-5) AB12(0,-5) AB13(0.5,-5) AB14(1,-5) AB15(1.5,-5) AB16(2,-5) AB17(2.5,-5) AB18(3,-5) AB19(3.5,-5) AB20(4,-5) AB21(4.5,-5) AB22(5,-5) AB23(5.5,-5) AC1(-5.5,-5.5) AC2(-5,-5.5) AC3(-4.5,-5.5) AC4(-4,-5.5) AC5(-3.5,-5.5) AC7(-2.5,-5.5) AC8(-2,-5.5) AC10(-1,-5.5) AC11(-0.5,-5.5) AC13(0.5,-5.5) AC14(1,-5.5) AC16(2,-5.5) AC17(2.5,-5.5) AC19(3.5,-5.5) AC20(4,-5.5) AC21(4.5,-5.5) AC22(5,-5.5) AC23(5.5,-5.5) B1(-5.5,5) B2(-5,5) B3(-4.5,5) B4(-4,5) B5(-3.5,5) B6(-3,5) B7(-2.5,5) B8(-2,5) B9(-1.5,5) B10(-1,5) B11(-0.5,5) B12(0,5) B13(0.5,5) B14(1,5) B15(1.5,5) B16(2,5) B17(2.5,5) B18(3,5) B19(3.5,5) B20(4,5) B21(4.5,5) B22(5,5) B23(5.5,5) C1(-5.5,4.5) C2(-5,4.5) C3(-4.5,4.5) C4(-4,4.5) C5(-3.5,4.5) C6(-3,4.5) C7(-2.5,4.5) C8(-2,4.5) C9(-1.5,4.5) C10(-1,4.5) C11(-0.5,4.5) C12(0,4.5) C13(0.5,4.5) C14(1,4.5) C15(1.5,4.5) C16(2,4.5) C17(2.5,4.5) C18(3,4.5) C19(3.5,4.5) C20(4,4.5) C21(4.5,4.5) C22(5,4.5) C23(5.5,4.5) D1(-5.5,4) D2(-5,4) D3(-4.5,4) D4(-4,4) D5(-3.5,4) D6(-3,4) D7(-2.5,4) D8(-2,4) D9(-1.5,4) D10(-1,4) D11(-0.5,4) D12(0,4) D13(0.5,4) D14(1,4) D15(1.5,4) D16(2,4) D17(2.5,4) D18(3,4) D19(3.5,4) D20(4,4) D21(4.5,4) D22(5,4) D23(5.5,4) E1(-5.5,3.5) E2(-5,3.5) E3(-4.5,3.5) E4(-4,3.5) E20(4,3.5) E21(4.5,3.5) E22(5,3.5) E23(5.5,3.5) F2(-5,3) F3(-4.5,3) F4(-4,3) F20(4,3) F21(4.5,3) F22(5,3) G1(-5.5,2.5) G2(-5,2.5) G3(-4.5,2.5) G4(-4,2.5) G20(4,2.5) G21(4.5,2.5) G22(5,2.5) G23(5.5,2.5) H1(-5.5,2) H2(-5,2) H3(-4.5,2) H4(-4,2) H20(4,2) H21(4.5,2) H22(5,2) H23(5.5,2) J2(-5,1.5) J3(-4.5,1.5) J4(-4,1.5) J20(4,1.5) J21(4.5,1.5) J22(5,1.5) K1(-5.5,1) K2(-5,1) K3(-4.5,1) K4(-4,1) K20(4,1) K21(4.5,1) K22(5,1) K23(5.5,1) L1(-5.5,0.5) L2(-5,0.5) L3(-4.5,0.5) L4(-4,0.5) L20(4,0.5) L21(4.5,0.5) L22(5,0.5) L23(5.5,0.5) M2(-5,0) M3(-4.5,0) M4(-4,0) M20(4,0) M21(4.5,0) M22(5,0) N1(-5.5,-0.5) N2(-5,-0.5) N3(-4.5,-0.5) N4(-4,-0.5) N20(4,-0.5) N21(4.5,-0.5) N22(5,-0.5) N23(5.5,-0.5) P1(-5.5,-1) P2(-5,-1) P3(-4.5,-1) P4(-4,-1) P20(4,-1) P21(4.5,-1) P22(5,-1) P23(5.5,-1) R2(-5,-1.5) R3(-4.5,-1.5) R4(-4,-1.5) R20(4,-1.5) R21(4.5,-1.5) R22(5,-1.5) T1(-5.5,-2) T2(-5,-2) T3(-4.5,-2) T4(-4,-2) T20(4,-2) T21(4.5,-2) T22(5,-2) T23(5.5,-2) U1(-5.5,-2.5) U2(-5,-2.5) U3(-4.5,-2.5) U4(-4,-2.5) U20(4,-2.5) U21(4.5,-2.5) U22(5,-2.5) U23(5.5,-2.5) V2(-5,-3) V3(-4.5,-3) V4(-4,-3) V20(4,-3) V21(4.5,-3) V22(5,-3) W1(-5.5,-3.5) W2(-5,-3.5) W3(-4.5,-3.5) W4(-4,-3.5) W20(4,-3.5) W21(4.5,-3.5) W22(5,-3.5) W23(5.5,-3.5) Y1(-5.5,-4) Y2(-5,-4) Y3(-4.5,-4) Y4(-4,-4) Y5(-3.5,-4) Y6(-3,-4) Y7(-2.5,-4) Y8(-2,-4) Y9(-1.5,-4) Y10(-1,-4) Y11(-0.5,-4) Y12(0,-4) Y13(0.5,-4) Y14(1,-4) Y15(1.5,-4) Y16(2,-4) Y17(2.5,-4) Y18(3,-4) Y19(3.5,-4) Y20(4,-4) Y21(4.5,-4) Y22(5,-4) Y23(5.5,-4)
  silkscreen extent -6.25,-6.07 6.07,6.25, body extent -6.07,-6.07 6.07,6.07, height 1.21
ICC_VFBGA96_9X13_P080 [mm]
  round 0.4 smd mask+0.05: A1(-3.2,6) A2(-2.4,6) A3(-1.6,6) A7(1.6,6) A8(2.4,6) A9(3.2,6) B1(-3.2,5.2) B2(-2.4,5.2) B3(-1.6,5.2) B7(1.6,5.2) B8(2.4,5.2) B9(3.2,5.2) C1(-3.2,4.4) C2(-2.4,4.4) C3(-1.6,4.4) C7(1.6,4.4) C8(2.4,4.4) C9(3.2,4.4) D1(-3.2,3.6) D2(-2.4,3.6) D3(-1.6,3.6) D7(1.6,3.6) D8(2.4,3.6) D9(3.2,3.6) E1(-3.2,2.8) E2(-2.4,2.8) E3(-1.6,2.8) E7(1.6,2.8) E8(2.4,2.8) E9(3.2,2.8) F1(-3.2,2) F2(-2.4,2) F3(-1.6,2) F7(1.6,2) F8(2.4,2) F9(3.2,2) G1(-3.2,1.2) G2(-2.4,1.2) G3(-1.6,1.2) G7(1.6,1.2) G8(2.4,1.2) G9(3.2,1.2) H1(-3.2,0.4) H2(-2.4,0.4) H3(-1.6,0.4) H7(1.6,0.4) H8(2.4,0.4) H9(3.2,0.4) J1(-3.2,-0.4) J2(-2.4,-0.4) J3(-1.6,-0.4) J7(1.6,-0.4) J8(2.4,-0.4) J9(3.2,-0.4) K1(-3.2,-1.2) K2(-2.4,-1.2) K3(-1.6,-1.2) K7(1.6,-1.2) K8(2.4,-1.2) K9(3.2,-1.2) L1(-3.2,-2) L2(-2.4,-2) L3(-1.6,-2) L7(1.6,-2) L8(2.4,-2) L9(3.2,-2) M1(-3.2,-2.8) M2(-2.4,-2.8) M3(-1.6,-2.8) M7(1.6,-2.8) M8(2.4,-2.8) M9(3.2,-2.8) N1(-3.2,-3.6) N2(-2.4,-3.6) N3(-1.6,-3.6) N7(1.6,-3.6) N8(2.4,-3.6) N9(3.2,-3.6) P1(-3.2,-4.4) P2(-2.4,-4.4) P3(-1.6,-4.4) P7(1.6,-4.4) P8(2.4,-4.4) P9(3.2,-4.4) R1(-3.2,-5.2) R2(-2.4,-5.2) R3(-1.6,-5.2) R7(1.6,-5.2) R8(2.4,-5.2) R9(3.2,-5.2) T1(-3.2,-6) T2(-2.4,-6) T3(-1.6,-6) T7(1.6,-6) T8(2.4,-6) T9(3.2,-6)
  silkscreen extent -4.72,-6.55 4.55,6.73, body extent -4.55,-6.55 4.55,6.55, height 1
ICC_WFQFN44-EPAD_5X6_P040 [mm]
  rect 0.8x0.2 smd mask+0.05: 1(-2.45,2.2) 2(-2.45,1.8) 3(-2.45,1.4) 4(-2.45,1) 5(-2.45,0.6) 6(-2.45,0.2) 7(-2.45,-0.2) 8(-2.45,-0.6) 9(-2.45,-1) 10(-2.45,-1.4) 11(-2.45,-1.8) 12(-2.45,-2.2) 23(2.45,-2.2) 24(2.45,-1.8) 25(2.45,-1.4) 26(2.45,-1) 27(2.45,-0.6) 28(2.45,-0.2) 29(2.45,0.2) 30(2.45,0.6) 31(2.45,1) 32(2.45,1.4) 33(2.45,1.8) 34(2.45,2.2)
  rect 0.2x0.8 smd mask+0.05: 13(-1.8,-2.95) 14(-1.4,-2.95) 15(-1,-2.95) 16(-0.6,-2.95) 17(-0.2,-2.95) 18(0.2,-2.95) 19(0.6,-2.95) 20(1,-2.95) 21(1.4,-2.95) 22(1.8,-2.95) 35(1.8,2.95) 36(1.4,2.95) 37(1,2.95) 38(0.6,2.95) 39(0.2,2.95) 40(-0.2,2.95) 41(-0.6,2.95) 42(-1,2.95) 43(-1.4,2.95) 44(-1.8,2.95)
  rect 3.6x4.6 smd paste-1.8 mask+0.05: ep(0,0)
  silkscreen extent -2.5,-3 2.5,3, body extent -2.5,-3 2.5,3, height 0.81
IND_2520_TOKO_DFE252012P [mm]
  rect 0.8x2 smd mask+0.05: 1(-1,0) 2(1,0)
  silkscreen extent -1.35,-1.12 1.35,1.12, body extent -1.35,-1.1 1.35,1.1, height 2
R0402 [mm]
  rect 0.51x0.7 smd mask+0.05: 1(-0.45,0) 2(0.45,0)
  silkscreen extent 0,-0.3 0,0.3, body extent -0.52,-0.3 0.52,0.3, height 0.4
SWI_JIUBABA_C-TS-02H-2-5-B-V-T_R_BLUE [mm] "BLUE"
  rect 0.75x1 smd mask+0.05: 1(-2.225,0.75) 2(2.225,0.75) 3(-2.225,-0.75) 4(2.225,-0.75)
  silkscreen extent -1.85,-1.6 1.85,1.6, body extent -2.45,-1.6 2.45,1.6, height 2.6

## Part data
B1: library part MCD-00172, "Switch HW SMD blue", Manufacturer=JIUBABA, Manufacturer_Part_Number="C-TS-02H-2.5-B-V-T/R BLUE"
C1 C2 C3 C4 C5 C6 C7 C8 C9 C10 C11 C12 C17 C19 C20 C21 C22 C23 C24 C25 C26 C61 C66 C71 C72 C78 C80 C82 C84 C85 C86 C87 C88 C89 C90: library part MCD-00006, "Capacitor, MLCC, 100nF, 16V, X7R, 10%, 0402, T=0.5mm", Alternate_Manufacturer=MURATA, Alternate_Manufacturer_Part_Number=GCM155R71C104KA55D, Manufacturer=YAGEO, Manufacturer_Part_Number=CC0402KRX7R7BB104, Package=C0402
C13 C14 C29 C34 C38 C40: library part MCD-00100, "Capacitor, MLCC, 22uF, 6V3, X5R, 20%, 0603, T=0,8mm", Manufacturer=MURATA, Manufacturer_Part_Number=GRM188R60J226MEA0J, Package=C0603
C15 C16: library part MCD-01124, "Capacitor, MLCC, 10uF, 10V, X5R, 10%, 0603, T=0.8mm", Manufacturer=MURATA, Manufacturer_Part_Number=GRM188R61A106KAAL, Package=C0603
C18 C31 C33 C39 C42 C46: library part MCD-00099, "Capacitor, MLCC, 10uF, 10V, X5R, 10%, 0603, T=0,8mm", Manufacturer=MURATA, Manufacturer_Part_Number=GRM188R61A106KE69D, Package=C0603
C30 C32 C35 C36 C37 C41 C45 C47 C48 C50 C53 C54 C55 C70 C75 C76 C77 C92 C94 C95 C96: library part MCD-00095, "Capacitor, MLCC, 1uF, 25V, X5R, 10%, 0402, T=0,5mm", Alternate_Manufacturer=MURATA, Alternate_Manufacturer_Part_Number=GRM155R60J105KE19, Manufacturer_Part_Number=GRM155R61E105KA12, Package=C0402
C43 C49 C51 C52: library part MCD-00096, "Capacitor, MLCC, 4.7uF, 6V3, X5R, 20%, 0402, T=0,5mm", Manufacturer=MURATA, Manufacturer_Part_Number=GRM155R60J475ME87, Package=C0402
C44 C97: library part MCD-00011, "Capacitor, MLCC, 10nF, 16V, X7R, 10%, 0402, T=0.5mm", Manufacturer=YAGEO, Manufacturer_Part_Number=CC0402KRX7R7BB103, Package=C0402
C56 C57: library part MCD-00198, "Capacitor, MLCC, 1nF, 16V, X7R, 10%, 0402, T=0.5mm", Manufacturer=YAGEO, Manufacturer_Part_Number=CC0402KRX7R7BB102, Package=C0402
C67 C68 C69: library part MCD-01823, "Capacitor,MLCC,2.2uF,6V3,X5R,10%,0402,T=0.5", Manufacturer=MURATA, Manufacturer_Part_Number=GRM155R60J225KE95D, Package=C0402
C79 C81 C83: library part MCD-00012, "Capacitor, MLCC, 2.2uF, 10V, X5R, 10%, 0603, T=0,8mm", Alternate_Manufacturer=KEMET, Alternate_Manufacturer_Part_Number=C0603C225K8PACTU, Manufacturer=YAGEO, Manufacturer_Part_Number=CC0603KRX5R6BB225, Package=C0603
L1 L2 L3 L4: library part MCD-01122, "Power Inductor ,1uH,4.3A max,+/-20%,0.042ohm,2520", Manufacturer=MURATA, Manufacturer_Part_Number=DFE252012P-1ROM{}P2, Package=2520
R1 R2 R3 R4 R5 R6 R7 R8 R9 R10 R11 R12 R13 R15 R16 R17 R18 R19 R20 R21 R22 R23 R24 R25: library part MCD-00054, "Resistor,56R,0402,1%,1/16W", Manufacturer=YAGEO, Manufacturer_Part_Number=RC0402FR-0756RL, Package=R0402
R14: library part MCD-00067, "Resistor,100R,0402,1%,1/16W", Manufacturer=YAGEO, Manufacturer_Part_Number=RC0402FR-07100RL, Package=R0402
R26 R28 R40: library part MCD-00053, "Resistor,10K,0402,1%,1/16W", Manufacturer=YAGEO, Manufacturer_Part_Number=RC0402FR-0710KL, Package=R0402
R27 R29: library part MCD-00120, "Resistor,240R,0402,1%,1/16W", Manufacturer=YAGEO, Manufacturer_Part_Number=RC0402FR-07240RL, Package=R0402
R31 R32 R33 R34 R42 R44: library part MCD-00061, "Resistor,1K,0402,1%,1/16W", Manufacturer=YAGEO, Manufacturer_Part_Number=RC0402FR-071KL, Package=R0402
R37 R38: library part MCD-00068, "Resistor,1K5,0402,1%,1/16W", Manufacturer=YAGEO, Manufacturer_Part_Number=RC0402FR-071K5L, Package=R0402
R41: library part MCD-00052, "Resistor,0R,0402,5%,1/16W", Manufacturer=YAGEO, Manufacturer_Part_Number=RC0402JR-070RL, Package=R0402
R43: library part MCD-00063, "Resistor,47K,0402,1%,1/16W", Manufacturer=YAGEO, Manufacturer_Part_Number=RC0402FR-0747KL, Package=R0402
U1: library part MCD-00677, "MPU TFBGA12x12 secure boot+crypto", Manufacturer=STMICROELECTRONICS, Manufacturer_Part_Number=STM32MP157CAC3
U2: library part MCD-01811, "Memory,DDR3L,4Gb,256Mbx16,933Mhz,1V35,TFBGA", Manufacturer=NANYA
U4: library part MCD-00303, "STM PMIC WFQFN 5.0x6.0x0.80 44L 0.4 pitch", Manufacturer=STMICROELECTRONICS, Manufacturer_Part_Number=STPMU1APQR
U5: library part MCD-00110, "Memory,e-MMC,4GB,3V3,WFBGA,153pins", Manufacturer=TOSHIBA, Manufacturer_Part_Number=THGBMDG5D1LBAIL

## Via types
v1: diameter 0.4, hole 0.2, Top Layer to Bottom Layer, tented both sides, 241 vias
v2: diameter 0.6, hole 0.3, Top Layer to Bottom Layer, tented both sides, 81 vias
v3: diameter 0.25, hole 0.1, Top Layer to Signal Layer 1, tented top, 72 vias
v4: diameter 0.25, hole 0.1, Top Layer to Signal Layer 1, tented both sides, 6 vias

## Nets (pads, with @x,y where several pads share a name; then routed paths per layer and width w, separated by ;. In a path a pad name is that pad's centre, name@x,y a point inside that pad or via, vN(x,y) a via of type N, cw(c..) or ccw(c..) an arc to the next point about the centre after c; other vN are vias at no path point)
3V3: C32.2 C40.2 C78.2 C79.2 L4.2 U4.22 U4.27 U5.E6 U5.F5 U5.J10 U5.K9 | length 51.3
  Top Layer w0.1: v3(12.25,81.45) U4.27@12.25,82.025
  Top Layer w0.175: U5.J10@27.7,88.475 U5.K9@28.2,88.975 v1(28.2,89.45) ; U5.E6@29.7,86.475 U5.F5@30.2,86.975 v1(30.625,86.975)
  Top Layer w0.2: 9.725,82.5 U4.22@9.9,82.675 9.9,82.491
  Top Layer w0.3: 9.625,82.5 9.725,82.5
  Top Layer w0.4: C32.2@7.7,80.075 7.9,80.075 8.187,80.362 8.635,80.81 8.635,81.41 9.725,82.5
  Signal Layer 1 w0.2: v2(11.575,74.9) 12.25,75.575 v3(12.25,81.45)
  Signal Layer 2 w0.3: v2(8.3,80.25) 7.075,79.025 7.075,76.475 8.65,74.9 v2(10.2,74.9) v2(10.9,74.9) v2(11.575,74.9)
  Bottom Layer w0.1: C79.2@27.35,89.575 C79.2@27.475,89.45
  Bottom Layer w0.13: C78.2@30.025,86.9 C78.2@30.125,87 ; v1@30.6,87 v1(30.625,86.975)
  Bottom Layer w0.3: v2(11.575,74.9) 17.275,80.6 17.275,82.625 18.775,84.125 22.575,84.125 25.25,86.8 25.25,87.475 C79.2@27.35,89.575 ; C79.2@27.475,89.45 28.175,89.45 28.188,89.437 29.325,88.3 29.325,87.6 C78.2@30.025,86.9 ; C78.2@30.125,87 v1@30.6,87
5V_VIN: C18.2 C31.2 C33.2 C39.2 C41.2 C51.2 R43.2 U4.8 U4.12 U4.19 U4.24 U4.28 U4.36 U4.37 | length 23.6
  Top Layer w0.2: 8.775,83.875 U4.19@9.9,83.875 ; 11.05,81.3 U4.24@11.05,82.025 ; U4.8@12.25,86.925 12.25,88.76 ; U4.28@12.65,82.025 12.65,80.975 13.625,80 C31.2@13.625,79.25 ; U4.36@15.8,83.075 16.45,83.075 C51.2@16.7,82.825 ; U4.37@15.8,83.475 16.825,83.475
  Top Layer w0.3: C41.2@7.7,83.325 8.25,83.875 8.775,83.875 ; v1(8.075,78.775) v1(8.55,78.775) v1(9,78.775) ; v2(18.575,81.45) 19.325,81.45 R43.2@19.461,81.586
  Top Layer w0.4: v2(4.725,83.15) v2(5.35,83.15) 5.735,82.765 7.335,82.765 7.7,83.13 C41.2@7.7,83.325
  Top Layer w0.45: 16.625,83.55 18.078,83.55 18.503,83.125 v2(18.575,83.125) ; C51.2@16.7,82.825 16.7,82.127 17.377,81.45 v2(18.575,81.45)
  Signal Layer 2 w0: 7.051,81.828 9.199,83.975
  other v1: 13.225,78.725 13.725,78.725 14.2,78.725
  other v2: 6.075,88.575 6.075,89.2 6.075,89.825 11.85,89.9 12.55,89.9 7.278,93.4
DDR_A0: R1.1 U1.L20 U2.N3 | length 49.6
  Top Layer w0.12: v1(35.625,63.5) 35.7,63.5 U1.L20@36,63.2 ; U2.N3@53.925,60.3 v1(54.325,60.7)
  Bottom Layer w0.12: v1(35.625,63.5) 41.35,63.5 41.565,63.715 41.951,63.715 42.066,63.6 42.225,63.6 42.475,63.85 42.475,65.95 41.6,66.825 41.6,73.525 42.1,74.025 47.825,74.025 48.5,73.35 48.5,61.375 49.85,60.025 53.8,60.025 54.325,60.55 v1(54.325,60.7) 54.325,60.95 54.725,61.35 54.725,61.65 55.7,62.625 56.025,62.625 R1.1@57.8,64.4
DDR_A1: R2.1 U1.P22 U2.P7 | length 52.1
  Top Layer w0.09: U1.P22@37,61.7 37.24,61.46 37.895,61.46 37.975,61.38 38.47,61.38 38.595,61.255 38.917,61.255 38.932,61.27 39.455,61.27 39.9,60.825 v1(40.175,60.825)
  Top Layer w0.12: U2.P7@53.125,57.1 v1(53.525,56.7)
  Bottom Layer w0.12: v1(40.175,60.825) 40.175,54.7 40.5,54.375 40.5,52 40.75,51.75 41.65,51.75 41.9,52 41.9,55.4 42.075,55.575 44.75,55.575 44.85,55.675 44.85,55.875 44.75,55.975 43.65,55.975 43.525,56.1 43.525,56.225 43.65,56.35 45.125,56.35 45.3,56.175 45.3,51.125 45.625,50.8 46.625,50.8 46.875,51.05 46.875,56.075 47.075,56.275 48.95,56.275 49.825,57.15 53.075,57.15 v1(53.525,56.7) 53.8,56.7 54.2,56.3 54.715,56.3 54.825,56.41 55.315,56.41 55.7,56.025 57.55,56.025 58.975,54.6 R2.1@60.75,54.6
DDR_A2: R3.1 U1.J20 U2.P3 | length 48.3
  Top Layer w0.12: v1(35.625,64.025) 35.8,64.2 U1.J20@36,64.2 ; U2.P3@53.125,60.3 v1(53.525,60.7)
  Bottom Layer w0.12: v1(35.625,64.025) 40,64.025 40.125,64.15 40.125,64.775 39.975,64.925 39.525,64.925 39.3,65.15 39.3,65.6 39.5,65.8 39.9,65.8 40.1,66 40.1,66.625 40.775,67.3 40.775,74.575 41.075,74.875 48.25,74.875 49.25,73.875 49.25,61.575 50.25,60.575 53.4,60.575 v1(53.525,60.7) 53.525,60.95 53.9,61.325 53.9,61.8 54.15,62.05 54.45,62.05 54.8,62.4 54.8,62.9 55.8,63.9 R3.1@55.8,64.4
DDR_A3: R4.1 U1.K22 U2.N2 | length 48.4
  Top Layer w0.09: U1.K22@37,63.7 37.24,63.46 39.265,63.46 39.325,63.4 39.656,63.4 39.691,63.435 40.259,63.435 40.294,63.4 41.275,63.4 41.95,64.075 v1(42.075,64.075)
  Top Layer w0.12: U2.N2@53.925,61.1 v1(54.325,61.5)
  Bottom Layer w0.12: v1(42.075,64.075) 42.075,64.925 41.9,65.1 40.925,65.1 40.675,65.35 40.675,65.675 41.15,66.15 41.15,73.65 41.95,74.45 48,74.45 48.875,73.575 48.875,61.475 50.05,60.3 53.675,60.3 53.925,60.55 53.925,60.925 54.125,61.125 54.125,61.3 v1(54.325,61.5) 54.325,61.6 55.025,62.3 55.025,62.625 56.175,63.775 56.6,63.775 56.8,63.975 R4.1@56.8,64.4
DDR_A4: R5.1 U1.V20 U2.P8 | length 44.9
  Top Layer w0.12: v1(35.6,59.9) 35.634,59.9 35.834,59.7 U1.V20@36,59.7 ; v1(52.625,54.9) 52.625,55.18 52.725,55.28 52.725,55.9 U2.P8@53.125,56.3
  Bottom Layer w0.12: v1(35.6,59.9) 35.634,59.9 36.434,59.1 36.434,57.291 36.6,57.125 36.875,57.125 37.625,56.375 37.625,52.775 38.175,52.225 38.175,48.4 39.2,47.375 48.05,47.375 48.15,47.475 48.15,47.7 48.075,47.775 45.35,47.775 45.275,47.85 45.275,48.1 45.35,48.175 49.275,48.175 49.65,48.55 49.65,54.3 50.75,55.4 52.125,55.4 v1(52.625,54.9) ; 52.68,54.695 52.8,54.575 52.8,53.7 52.95,53.55 53.2,53.55 R5.1@53.705,53.045
DDR_A5: R6.1 U1.H20 U2.P2 | length 46.5
  Top Layer w0.12: v1(35.125,64.175) 35.65,64.7 U1.H20@36,64.7 ; U2.P2@53.125,61.1 v1(53.525,61.5)
  Bottom Layer w0.12: v1(35.125,64.175) 35.425,64.475 38.45,64.475 38.8,64.825 38.8,66.1 40.375,67.675 40.375,74.775 40.9,75.3 48.4,75.3 49.6,74.1 49.6,61.7 50.45,60.85 52.875,60.85 v1(53.525,61.5) 53.525,62.245 54.8,63.52 R6.1@54.8,64.4
DDR_A6: R7.1 U1.W20 U2.R8 | length 44.2
  Top Layer w0.12: v1(35.625,59.4) 35.825,59.2 U1.W20@36,59.2 ; v1(51.905,55) 51.905,55.88 U2.R8@52.325,56.3 ; U2.R8@52.312,56.35 U2.R8@52.325,56.35
  Bottom Layer w0.12: v1(35.625,59.4) 36,59.025 36,56.775 36.15,56.625 36.775,56.625 37.125,56.275 37.125,52.65 37.75,52.025 37.75,48.2 39,46.95 51.125,46.95 51.225,47.05 51.225,47.225 51.075,47.375 48.65,47.375 48.575,47.45 48.575,47.625 48.7,47.75 49.975,47.75 50.15,47.925 50.15,54.4 50.925,55.175 51.73,55.175 v1(51.905,55) 52.325,54.58 52.395,54.58 52.53,54.445 52.53,53.22 R7.1@52.705,53.045
DDR_A7: R8.1 U1.E20 U2.R2 | length 43.6
  Top Layer w0.12: v1(35.625,66) 35.825,66.2 U1.E20@36,66.2 ; v1@51.925,62.419 51.925,61.5 U2.R2@52.325,61.1
  Bottom Layer w0.12: v1(35.625,66) 37.2,66 37.55,66.35 37.55,67.775 38,68.225 38.725,68.225 39.075,68.575 39.075,75.825 39.825,76.575 49.225,76.575 50.725,75.075 50.725,62.175 50.9,62 51.465,62 v1(51.905,62.44) 51.905,62.97 51.6,63.275 51.6,64.2 R8.1@51.8,64.4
